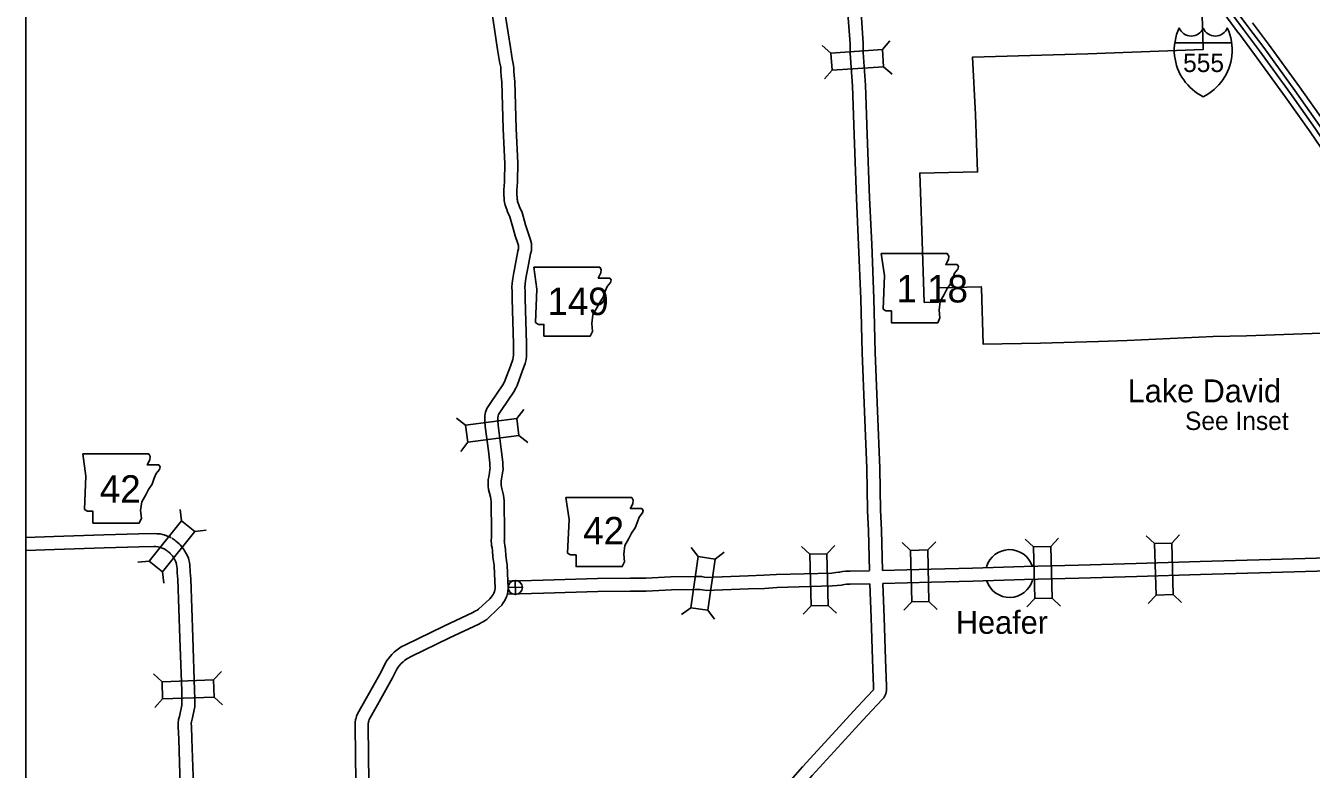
# Model space of a CAD drawing. Extents: x -117616 to 64730, y 54117 to 789866.
# Drawn here: x 61556.6 to 61852.8, y 55637.7 to 55809 of the extents above; entities that cross this region are included whole.
import ezdxf

# ---------------------------------------------------------------- set-up
doc = ezdxf.new("R2010")
doc.units = 0
for name, color, linetype in [('10', 7, 'Continuous'), ('19', 7, 'Continuous'), ('20', 7, 'Continuous'), ('21', 7, 'Continuous'), ('23', 7, 'Continuous'), ('24', 7, 'Continuous'), ('26', 7, 'Continuous'), ('6', 7, 'Continuous'), ('R_No Plot', 7, 'Continuous')]:
    doc.layers.add(name, color=color, linetype=linetype)

msp = doc.modelspace()

# ---------------------------------------------------------------- linework, layer by layer
at = {"layer": '10'}
for points in [[(61746.48, 55814.41), (61746.45, 55814.25), (61746.29, 55813.2), (61746.16, 55811.77), (61746.12, 55810.78), (61746.52, 55804.8), (61746.56, 55802.68)], [(61749.53, 55814.43), (61749.51, 55814.3), (61749.41, 55813.76), (61749.27, 55812.83), (61749.15, 55811.57), (61749.12, 55810.82), (61749.52, 55804.93), (61749.56, 55802.73)], [(61663.93, 55812.44), (61663.93, 55812.34), (61664.03, 55811.62), (61664.26, 55810.27), (61665.29, 55803.53), (61665.81, 55800.31)], [(61666.96, 55812.38), (61667, 55812.08), (61667.22, 55810.74), (61668.26, 55803.99), (61668.76, 55800.9)], [(61746.56, 55802.6), (61747.07, 55795.13), (61747.49, 55783.84), (61748, 55769.2), (61748.5, 55758.54), (61748.97, 55746.08), (61749.34, 55733.61), (61749.88, 55720.15), (61750.37, 55707.04), (61750.54, 55697.39)], [(61749.56, 55802.8), (61750.07, 55795.28), (61750.49, 55783.95), (61750.99, 55769.32), (61751.5, 55758.67), (61751.97, 55746.18), (61752.34, 55733.72), (61752.88, 55720.27), (61753.37, 55707.12), (61753.54, 55697.44)], [(61665.82, 55800.32), (61666.03, 55799.4), (61666.05, 55799.04), (61666.08, 55798.4), (61666.11, 55797.32), (61666.25, 55795.96), (61666.62, 55785.22), (61666.96, 55777.2), (61666.97, 55776.48), (61666.94, 55775.85), (61666.9, 55774.75), (61666.91, 55773.03), (61666.76, 55771.2), (61666.75, 55770.5), (61666.77, 55769.8), (61666.8, 55769.38), (61666.85, 55768.72), (61666.91, 55768.31), (61667.02, 55767.66), (61667.42, 55766.65), (61667.6, 55766.15), (61668.15, 55764.97), (61668.86, 55762.28), (61669.39, 55760.56), (61670, 55758.82), (61670.1, 55758.38), (61670.11, 55758.16), (61670.09, 55757.61), (61669.96, 55757.04), (61669.59, 55754.95), (61669.36, 55753.77), (61669.19, 55752.94), (61669.04, 55752.18), (61668.78, 55750.78), (61668.63, 55749.69), (61668.61, 55748.73), (61668.63, 55747.8), (61668.66, 55745.98), (61668.99, 55735.74), (61668.98, 55734.48), (61668.98, 55733.67), (61668.96, 55733.09), (61668.92, 55732.6), (61668.78, 55732.1), (61668.25, 55730.6), (61666.97, 55727.17), (61666.89, 55726.93), (61666.51, 55726.3), (61663.78, 55722.23), (61663.3, 55721.52), (61662.86, 55720.82), (61662.53, 55719.98), (61662.37, 55719.11), (61662.33, 55717.86), (61662.45, 55716.67), (61663.18, 55711.07), (61663.49, 55708.21), (61663.55, 55707.52), (61663.56, 55707.05), (61663.53, 55706.77), (61663.43, 55706.01), (61663.25, 55705.08), (61663.17, 55704.45), (61663.11, 55703.98), (61663.11, 55703.5), (61663.13, 55702.96), (61663.23, 55702.17), (61663.43, 55701.36), (61663.64, 55700.51), (61663.75, 55699.93), (61663.79, 55699.31), (61663.82, 55698.5), (61663.88, 55693.16)], [(61668.74, 55801), (61669, 55799.85), (61669.05, 55799.21), (61669.08, 55798.51), (61669.11, 55797.52), (61669.24, 55796.16), (61669.62, 55785.33), (61669.96, 55777.29), (61669.97, 55776.43), (61669.94, 55775.73), (61669.9, 55774.7), (61669.91, 55772.91), (61669.76, 55771.07), (61669.75, 55770.53), (61669.77, 55769.93), (61669.79, 55769.58), (61669.83, 55769.06), (61669.87, 55768.79), (61669.92, 55768.48), (61670.23, 55767.71), (61670.38, 55767.29), (61670.98, 55766), (61671.75, 55763.1), (61672.24, 55761.49), (61672.89, 55759.65), (61673.08, 55758.8), (61673.11, 55758.19), (61673.08, 55757.22), (61672.9, 55756.45), (61672.54, 55754.39), (61672.3, 55753.18), (61672.13, 55752.36), (61671.99, 55751.61), (61671.74, 55750.3), (61671.63, 55749.46), (61671.61, 55748.73), (61671.63, 55747.85), (61671.66, 55746.05), (61671.99, 55735.77), (61671.98, 55734.47), (61671.98, 55733.63), (61671.96, 55732.9), (61671.88, 55732.08), (61671.65, 55731.21), (61671.07, 55729.57), (61669.79, 55726.14), (61669.62, 55725.65), (61669.04, 55724.69), (61666.27, 55720.56), (61665.81, 55719.88), (61665.55, 55719.46), (61665.43, 55719.15), (61665.36, 55718.79), (61665.34, 55717.96), (61665.43, 55717), (61666.16, 55711.43), (61666.48, 55708.5), (61666.55, 55707.65), (61666.56, 55706.92), (61666.51, 55706.43), (61666.39, 55705.54), (61666.21, 55704.6), (61666.14, 55704.07), (61666.11, 55703.78), (61666.11, 55703.58), (61666.12, 55703.22), (61666.18, 55702.72), (61666.34, 55702.08), (61666.57, 55701.16), (61666.73, 55700.32), (61666.79, 55699.46), (61666.82, 55698.56), (61666.88, 55693.19)], [(61751, 55683.48), (61750.76, 55692.67), (61750.54, 55697.34)], [(61754, 55683.55), (61753.75, 55692.78), (61753.53, 55697.48)], [(61664.51, 55684.75), (61664.24, 55686.6), (61664.12, 55688.04), (61664.04, 55688.83), (61663.93, 55689.3), (61663.88, 55689.77), (61663.85, 55690.31), (61663.86, 55690.69), (61663.89, 55691), (61663.91, 55691.24), (61663.88, 55693.15)], [(61667.47, 55685.18), (61667.22, 55686.94), (61667.11, 55688.32), (61667, 55689.32), (61666.89, 55689.8), (61666.87, 55690.03), (61666.85, 55690.33), (61666.86, 55690.5), (61666.88, 55690.73), (61666.91, 55691.12), (61666.88, 55693.2)], [(61556.57, 55691.12), (61563.09, 55691.36), (61574.58, 55691.72), (61582.64, 55691.99), (61586.22, 55692.06), (61586.81, 55692), (61587.54, 55691.94), (61588.07, 55691.8), (61588.48, 55691.71), (61588.99, 55691.52), (61589.28, 55691.42), (61589.75, 55691.25), (61590.12, 55691.03)], [(61590.21, 55690.97), (61590.92, 55690.48), (61591.19, 55690.27), (61591.5, 55690.02), (61591.93, 55689.65), (61591.98, 55689.58), (61592.15, 55689.46), (61592.63, 55688.91), (61592.88, 55688.58), (61593.22, 55688), (61593.43, 55687.65), (61593.76, 55687.02), (61594.07, 55686.35), (61594.19, 55685.94), (61594.29, 55685.34), (61594.36, 55684.82), (61594.42, 55684.32), (61594.49, 55683.67), (61594.5, 55683.14), (61594.59, 55681.6), (61595.06, 55668.06), (61595.5, 55655.95), (61595.58, 55653.98), (61595.58, 55653.28), (61595.57, 55652.74), (61595.52, 55652.09), (61594.91, 55649.25), (61594.77, 55648.69), (61594.73, 55648.28), (61594.74, 55647.61), (61594.85, 55644.78), (61595.2, 55634.02)], [(61556.57, 55688.11), (61563.19, 55688.36), (61574.67, 55688.72), (61582.72, 55688.99), (61586.11, 55689.05), (61586.55, 55689.01), (61587.04, 55688.97), (61587.35, 55688.89), (61587.62, 55688.83), (61587.98, 55688.69), (61588.28, 55688.59), (61588.47, 55688.52), (61588.6, 55688.45)], [(61588.5, 55688.51), (61589.15, 55688.06), (61589.33, 55687.92), (61589.57, 55687.72), (61589.75, 55687.57), (61589.88, 55687.41), (61590.1, 55687.24), (61590.31, 55687.01), (61590.38, 55686.91), (61590.64, 55686.46), (61590.83, 55686.16), (61591.07, 55685.7), (61591.26, 55685.29), (61591.26, 55685.26), (61591.32, 55684.92), (61591.38, 55684.43), (61591.44, 55683.97), (61591.49, 55683.47), (61591.51, 55683.01), (61591.59, 55681.46), (61592.06, 55667.95), (61592.51, 55655.84), (61592.58, 55653.93), (61592.58, 55653.3), (61592.57, 55652.86), (61592.55, 55652.51), (61591.99, 55649.93), (61591.81, 55649.21), (61591.73, 55648.41), (61591.74, 55647.52), (61591.85, 55644.68), (61592.2, 55633.91)], [(61754.01, 55683.55), (61765.23, 55683.81), (61774.72, 55684.06), (61786.64, 55684.43), (61799.18, 55684.76), (61812.48, 55685.15), (61827.21, 55685.59), (61843.45, 55686.05), (61859.29, 55686.54), (61868.77, 55686.95), (61880.1, 55687.4), (61902.46, 55688.18)], [(61632.64, 55634.72), (61632.48, 55647.65), (61632.5, 55648.25), (61632.52, 55648.53), (61632.6, 55649.19), (61632.69, 55649.52), (61632.82, 55649.94), (61633.05, 55650.48), (61635.02, 55654.07), (61638.45, 55660.2), (61639.5, 55662.27), (61639.89, 55662.87), (61640.21, 55663.36), (61640.95, 55664.17), (61641.48, 55664.69), (61641.9, 55665.07), (61642.45, 55665.5), (61643.07, 55665.91), (61644.07, 55666.39), (61652.95, 55670.71), (61659.63, 55673.87), (61659.95, 55674.04), (61660.25, 55674.2), (61660.52, 55674.33), (61660.6, 55674.38), (61660.88, 55674.58), (61663.51, 55677.02), (61663.86, 55677.35), (61664.31, 55678), (61664.32, 55678.02), (61664.44, 55678.3), (61664.61, 55678.67), (61664.63, 55678.76), (61664.65, 55678.92), (61664.71, 55679.56), (61664.56, 55682.72), (61664.52, 55684.65), (61664.51, 55684.74)], [(61635.64, 55634.75), (61635.48, 55647.61), (61635.5, 55648.09), (61635.51, 55648.24), (61635.55, 55648.61), (61635.57, 55648.69), (61635.64, 55648.91), (61635.75, 55649.17), (61637.64, 55652.62), (61641.1, 55658.79), (61642.1, 55660.78), (61642.4, 55661.24), (61642.58, 55661.51), (61643.11, 55662.09), (61643.54, 55662.51), (61643.82, 55662.76), (61644.2, 55663.06), (61644.55, 55663.29), (61645.38, 55663.69), (61654.25, 55668.01), (61660.97, 55671.19), (61661.34, 55671.39), (61661.58, 55671.51), (61662, 55671.7), (61662.32, 55671.92), (61662.79, 55672.27), (61665.55, 55674.83), (61666.32, 55675.55), (61666.45, 55675.82), (61666.77, 55676.28), (61666.99, 55676.6), (61667.19, 55677.12), (61667.44, 55677.63), (61667.59, 55678.21), (61667.64, 55678.63), (61667.71, 55679.5), (61667.56, 55682.82), (61667.52, 55684.9), (61667.47, 55685.19)], [(61754.11, 55680.55), (61765.3, 55680.82), (61774.81, 55681.06), (61786.72, 55681.43), (61799.27, 55681.76), (61812.57, 55682.15), (61827.3, 55682.59), (61843.54, 55683.05), (61859.4, 55683.54), (61868.89, 55683.96), (61880.22, 55684.4), (61902.5, 55685.18)], [(61667.69, 55681.07), (61675.83, 55681.3), (61688.33, 55681.69), (61695.86, 55681.74), (61699.48, 55681.78), (61705.26, 55682.03), (61710.74, 55682.12), (61711.64, 55682.17), (61712.35, 55682.11), (61712.95, 55682.02), (61713.64, 55681.93), (61715.06, 55681.99), (61723.02, 55682.3), (61726.63, 55682.41), (61729.49, 55682.6)], [(61729.55, 55682.6), (61742.29, 55682.94), (61743.25, 55683.02), (61743.97, 55683.1), (61744.18, 55683.16), (61744.78, 55683.28), (61745.55, 55683.37), (61746.58, 55683.34), (61750.99, 55683.47)], [(61667.58, 55678.07), (61675.91, 55678.31), (61688.39, 55678.69), (61695.89, 55678.74), (61699.56, 55678.78), (61705.35, 55679.03), (61710.85, 55679.12), (61711.58, 55679.16), (61712, 55679.13), (61712.55, 55679.05), (61713.51, 55678.93), (61715.17, 55678.99), (61723.13, 55679.3), (61726.78, 55679.41), (61729.69, 55679.61)], [(61729.63, 55679.6), (61742.44, 55679.95), (61743.55, 55680.03), (61744.53, 55680.15), (61744.85, 55680.23), (61745.25, 55680.31), (61745.69, 55680.36), (61746.58, 55680.34), (61751.08, 55680.47)], [(61730.72, 55632.78), (61735.53, 55638.31), (61742.37, 55645.74), (61747.29, 55651.1), (61750.47, 55654.54), (61751.81, 55655.93), (61751.89, 55656.03), (61751.89, 55656.05), (61751.9, 55656.12), (61751.9, 55656.82), (61751.72, 55663), (61751.38, 55672.62), (61751.1, 55680.47)], [(61732.98, 55630.81), (61737.77, 55636.31), (61744.58, 55643.71), (61749.5, 55649.06), (61752.66, 55652.48), (61754.04, 55653.93), (61754.29, 55654.23), (61754.57, 55654.62), (61754.77, 55655.12), (61754.85, 55655.53), (61754.9, 55655.91), (61754.9, 55656.87), (61754.72, 55663.09), (61754.38, 55672.72), (61754.09, 55680.54)]]:
    msp.add_lwpolyline(points, dxfattribs=at)
at = {"layer": '19'}
for points in [[(61829.02, 55816.87), (61836.06, 55807.28)], [(61830.72, 55816.88), (61837.16, 55808.09)], [(61832.22, 55816.94), (61838.17, 55808.83)], [(61863.07, 55770.24), (61861.99, 55772.84), (61860.12, 55777.32), (61859.42, 55778.92), (61858.53, 55780.4), (61854.72, 55786.01), (61848.98, 55794.08), (61841.85, 55803.93), (61838.17, 55808.83)], [(61864.34, 55770.77), (61863.26, 55773.37), (61861.38, 55777.86), (61860.65, 55779.55), (61859.69, 55781.15), (61855.85, 55786.8), (61850.1, 55794.88), (61842.95, 55804.75), (61839.27, 55809.66)], [(61860.66, 55769.2), (61859.57, 55771.83), (61857.71, 55776.29), (61857.09, 55777.71), (61856.32, 55778.99), (61852.56, 55784.51), (61846.85, 55792.55), (61839.74, 55802.38), (61836.07, 55807.26)], [(61861.92, 55769.74), (61860.84, 55772.36), (61858.97, 55776.83), (61858.31, 55778.34), (61857.47, 55779.73), (61853.69, 55785.3), (61847.97, 55793.35), (61840.84, 55803.19), (61837.17, 55808.08)]]:
    msp.add_lwpolyline(points, dxfattribs=at)
at = {"layer": '20'}
for p, q in [((61742.11, 55802.68), (61740.12, 55804.41)), ((61753.96, 55803.48), (61755.7, 55805.47)), ((61742.38, 55798.72), (61740.64, 55796.74)), ((61754.23, 55799.53), (61756.22, 55797.79)), ((61669.71, 55718.51), (61671.32, 55720.6)), ((61657.93, 55716.98), (61655.84, 55718.59)), ((61670.22, 55714.59), (61672.31, 55712.98)), ((61658.44, 55713.05), (61656.83, 55710.96)), ((61592.44, 55694.96), (61592.15, 55697.59)), ((61595.53, 55692.48), (61598.15, 55692.77)), ((61764.43, 55688.24), (61766.25, 55690.15)), ((61788.79, 55688.93), (61786.88, 55690.74)), ((61792.75, 55689.03), (61794.57, 55690.95)), ((61816.67, 55689.72), (61814.75, 55691.53)), ((61820.63, 55689.84), (61822.44, 55691.76)), ((61711.51, 55686.71), (61709.93, 55688.83)), ((61715.43, 55686.15), (61717.54, 55687.73)), ((61737.23, 55687.25), (61735.31, 55689.06)), ((61741.19, 55687.35), (61743, 55689.27)), ((61760.47, 55688.14), (61758.56, 55689.97)), ((61585.01, 55685.7), (61582.38, 55685.41)), ((61588.1, 55683.22), (61588.38, 55680.59)), ((61737.54, 55675.37), (61735.73, 55673.46)), ((61741.5, 55675.48), (61743.42, 55673.66)), ((61760.75, 55676.27), (61758.92, 55674.36)), ((61764.71, 55676.36), (61766.62, 55674.54)), ((61789.11, 55677.05), (61787.29, 55675.14)), ((61793.06, 55677.16), (61794.98, 55675.34)), ((61817.03, 55677.84), (61815.22, 55675.92)), ((61820.98, 55677.96), (61822.91, 55676.15)), ((61709.82, 55674.95), (61707.71, 55673.37)), ((61713.74, 55674.39), (61715.32, 55672.28)), ((61587.99, 55657.9), (61586.05, 55659.69)), ((61599.86, 55658.34), (61601.66, 55660.27)), ((61588.13, 55653.94), (61586.34, 55652)), ((61600.01, 55654.38), (61601.94, 55652.58))]:
    msp.add_line(p, q, dxfattribs=at)
for points in [[(61753.96, 55803.48), (61742.11, 55802.68), (61742.38, 55798.72), (61754.23, 55799.53)], [(61658.44, 55713.05), (61670.22, 55714.59), (61669.71, 55718.51), (61657.93, 55716.98)], [(61588.1, 55683.22), (61595.53, 55692.48), (61592.44, 55694.96), (61585.01, 55685.7)], [(61737.23, 55687.25), (61737.54, 55675.37), (61741.5, 55675.48), (61741.19, 55687.35)], [(61764.71, 55676.36), (61764.43, 55688.24), (61760.47, 55688.14), (61760.75, 55676.27)], [(61793.06, 55677.16), (61792.75, 55689.03), (61788.79, 55688.93), (61789.11, 55677.05)], [(61820.98, 55677.96), (61820.63, 55689.84), (61816.67, 55689.72), (61817.03, 55677.84)], [(61713.74, 55674.39), (61715.43, 55686.15), (61711.51, 55686.71), (61709.82, 55674.95)], [(61599.86, 55658.34), (61587.99, 55657.9), (61588.13, 55653.94), (61600.01, 55654.38)]]:
    msp.add_lwpolyline(points, close=True, dxfattribs=at)
at = {"layer": '21'}
for points in [[(61753.69, 55756.5), (61754.45, 55751.42), (61754.12, 55743.72), (61754.79, 55743.3), (61756.06, 55743.3), (61756.06, 55740.59), (61766.72, 55740.59), (61767.23, 55741.69), (61767.06, 55743.47), (61767.31, 55745.5), (61768.24, 55747.11), (61768.83, 55748.29), (61769.68, 55749.56), (61770.19, 55750.91), (61770.61, 55752.01), (61771.37, 55752.94), (61771.54, 55753.54), (61771.2, 55753.96), (61768.58, 55753.96), (61769.17, 55755.14), (61769.26, 55755.9), (61768.91, 55756.49)], [(61673.62, 55753.4), (61674.38, 55748.32), (61674.04, 55740.62), (61674.72, 55740.2), (61675.99, 55740.2), (61675.99, 55737.49), (61686.65, 55737.49), (61687.15, 55738.59), (61686.99, 55740.37), (61687.24, 55742.4), (61688.17, 55744.01), (61688.76, 55745.19), (61689.61, 55746.46), (61690.12, 55747.81), (61690.54, 55748.91), (61691.3, 55749.84), (61691.47, 55750.44), (61691.13, 55750.86), (61688.51, 55750.86), (61689.1, 55752.04), (61689.18, 55752.8), (61688.83, 55753.39)], [(61569.7, 55710.36), (61570.46, 55705.28), (61570.12, 55697.58), (61570.8, 55697.16), (61572.07, 55697.16), (61572.07, 55694.45), (61582.72, 55694.45), (61583.23, 55695.55), (61583.06, 55697.33), (61583.32, 55699.36), (61584.25, 55700.97), (61584.84, 55702.15), (61585.68, 55703.42), (61586.19, 55704.77), (61586.62, 55705.87), (61587.38, 55706.8), (61587.55, 55707.4), (61587.21, 55707.82), (61584.58, 55707.82), (61585.18, 55709), (61585.26, 55709.77), (61584.91, 55710.35)], [(61681.02, 55700.31), (61681.78, 55695.24), (61681.44, 55687.54), (61682.12, 55687.11), (61683.39, 55687.11), (61683.39, 55684.41), (61694.04, 55684.41), (61694.55, 55685.51), (61694.38, 55687.28), (61694.64, 55689.31), (61695.57, 55690.92), (61696.16, 55692.11), (61697.01, 55693.37), (61697.51, 55694.73), (61697.94, 55695.83), (61698.7, 55696.76), (61698.87, 55697.35), (61698.53, 55697.77), (61695.91, 55697.77), (61696.5, 55698.96), (61696.58, 55699.72), (61696.23, 55700.3)]]:
    msp.add_lwpolyline(points, close=True, dxfattribs=at)
at = {"layer": '23'}
msp.add_line((61821.35, 55805.03), (61834.46, 55805.03), dxfattribs=at)
for centre, radius, start, end in [((61833.53, 55803.32), 12.3, 155.2204, 185.7928), ((61825.14, 55809.6), 3, 202.1459, 337.3414), ((61830.67, 55809.6), 3, 202.6586, 337.8541), ((61822.28, 55803.32), 12.3, 354.2072, 24.7796), ((61833.31, 55803.42), 12.09, 186.3923, 243.4571), ((61822.5, 55803.42), 12.09, 296.5429, 353.6077)]:
    msp.add_arc(centre, radius, start, end, dxfattribs=at)
at = {"layer": '24'}
for start, end in [(19.0256, 163.7151), (198.8247, 343.7151)]:
    msp.add_arc((61783.26, 55682.82), 5.5, start, end, dxfattribs=at)
at = {"layer": '26'}
for p, q in [((61669.42, 55677.98), (61669.34, 55681.24)), ((61667.75, 55679.57), (61671.01, 55679.65))]:
    msp.add_line(p, q, dxfattribs=at)
msp.add_circle((61669.38, 55679.61), 1.63, dxfattribs=at)
at = {"layer": '6'}
msp.add_lwpolyline([(61854.63, 55817.67), (61841.93, 55817.22), (61828.33, 55816.75), (61827.5, 55816.72), (61827.88, 55803.48), (61801.29, 55802.53), (61774.77, 55801.76), (61775.39, 55788.5), (61775.9, 55775.32), (61762.56, 55775.04), (61763.07, 55761.81), (61763.62, 55745.27), (61766.93, 55745.34), (61766.82, 55748.65), (61776.76, 55748.88), (61776.77, 55748.52), (61777.22, 55735.62), (61790.42, 55735.89), (61803.79, 55736.26), (61810.35, 55736.48), (61830.17, 55737.37), (61837.86, 55737.55), (61857.32, 55738.23)], dxfattribs=at)
at = {"layer": 'R_No Plot'}
msp.add_lwpolyline([(61556.57, 56155.54), (62285.97, 56155.54), (62285.97, 55371.05), (61556.57, 55371.05)], close=True, dxfattribs=at)

# ---------------------------------------------------------------- texts
at = {"layer": '20'}
msp.add_text('See Inset', height=4.224, dxfattribs=at).set_placement((61823.71, 55715.88))
at = {"layer": '21'}
for s, p in [('1 18', (61757.2, 55745.24)), ('149', (61676.78, 55742.34)), ('42', (61573.65, 55699.12)), ('42', (61685.03, 55689.51))]:
    msp.add_text(s, height=6.336, dxfattribs=at).set_placement(p)
at = {"layer": '23'}
msp.add_text('555', height=4.224, dxfattribs=at).set_placement((61823.26, 55798.31))
at = {"layer": '24'}
for s, p in [('Lake David', (61810.5, 55722.25)), ('Heafer', (61770.92, 55668.94))]:
    msp.add_text(s, height=5.28, dxfattribs=at).set_placement(p)

doc.saveas('drawing.dxf')
